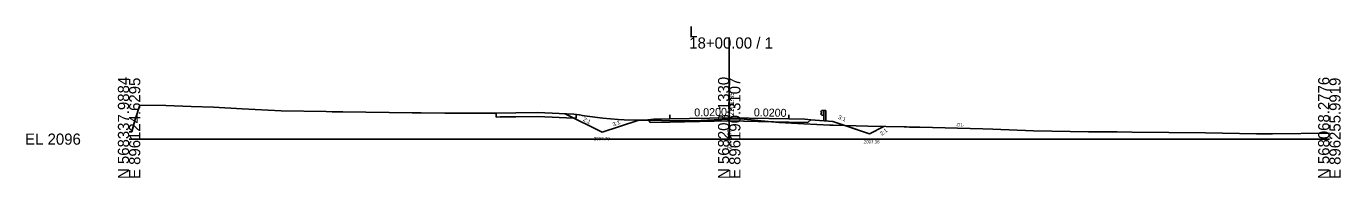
# Model space of a CAD drawing. Extents: x -26 to 1603, y -10 to 13527.
# Drawn here: x -25.7 to 302.8, y 5490.3 to 5528.3 of the extents above; entities that cross this region are included whole.
import ezdxf

# ---------------------------------------------------------------- set-up
doc = ezdxf.new("R2010")
doc.units = 0
for name, color, linetype in [('Default', 7, 'Continuous'), ('Exist XS Center Line Elevation Label', 7, 'Continuous'), ('Exist XS Ground Line', 7, 'Continuous'), ('Old_Level_61', 7, 'Continuous'), ('Old_Level_63', 7, 'Continuous'), ('Prop XS Ditch Slope Text', 7, 'Continuous'), ('Prop XS Ditch Standard Text', 7, 'Continuous'), ('Prop XS Earthwork Shape', 7, 'Continuous'), ('Prop XS EOT Tick Mark', 7, 'Continuous'), ('Prop XS Finish Grade', 7, 'Continuous'), ('Prop XS Finish Grade Earthwork', 7, 'Continuous'), ('Prop XS Finish Grade Paved Shoulder', 7, 'Continuous'), ('Prop XS Finish Grade Pavement', 7, 'Continuous'), ('Prop XS Guardrail', 7, 'Continuous'), ('Prop XS Side Slope Text', 7, 'Continuous'), ('Prop XS Subgrade Earthwork', 7, 'Continuous'), ('Prop XSC Text', 7, 'Continuous')]:
    doc.layers.add(name, color=color, linetype=linetype)

msp = doc.modelspace()

# ---------------------------------------------------------------- linework, layer by layer
at = {"layer": 'Exist XS Ground Line'}
for p, q in [((1.47, 5504.68), (2.66, 5508.5)), ((2.66, 5508.5), (9.21, 5508.43)), ((9.21, 5508.43), (15.51, 5508.21)), ((15.51, 5508.21), (21.06, 5507.97)), ((21.06, 5507.97), (28.3, 5507.58)), ((28.3, 5507.58), (38.03, 5507.12)), ((38.03, 5507.12), (49.22, 5506.88)), ((49.22, 5506.88), (50.76, 5506.85)), ((50.76, 5506.85), (53.46, 5506.83)), ((53.46, 5506.83), (70.76, 5506.62)), ((70.76, 5506.62), (73.04, 5506.59)), ((73.04, 5506.59), (78.93, 5506.49)), ((78.93, 5506.49), (90.15, 5506.53)), ((90.15, 5506.53), (91.73, 5506.53)), ((91.73, 5506.53), (96.69, 5506.61)), ((96.69, 5506.61), (102.07, 5506.7)), ((102.07, 5506.7), (111.16, 5506.24)), ((111.16, 5506.24), (111.77, 5506.21)), ((111.77, 5506.21), (112.54, 5506.05)), ((0.68, 5501.79), (1.47, 5504.68)), ((112.54, 5506.05), (113.29, 5505.9)), ((113.29, 5505.9), (113.8, 5505.8)), ((113.8, 5505.8), (118.37, 5505.29)), ((118.37, 5505.29), (122.24, 5504.89)), ((122.24, 5504.89), (123.74, 5504.83)), ((123.74, 5504.83), (133.06, 5504.65)), ((133.06, 5504.65), (137.76, 5504.56)), ((137.76, 5504.56), (141.34, 5504.61)), ((141.34, 5504.61), (146.25, 5504.86)), ((146.25, 5504.86), (150, 5504.98)), ((150, 5504.98), (152.88, 5505.07)), ((152.88, 5505.07), (160.6, 5504.36)), ((160.6, 5504.36), (162.47, 5504.19)), ((162.47, 5504.19), (168.69, 5503.86)), ((168.69, 5503.86), (175.19, 5503.5)), ((175.19, 5503.5), (175.99, 5503.48)), ((175.99, 5503.48), (184.67, 5503.23)), ((184.67, 5503.23), (193.7, 5503.07)), ((193.7, 5503.07), (194.29, 5503.06)), ((194.29, 5503.06), (195.07, 5503.02)), ((195.07, 5503.02), (197.68, 5502.99)), ((197.68, 5502.99), (213.4, 5502.6)), ((0, 5501.79), (0.68, 5501.79)), ((213.4, 5502.6), (215.93, 5502.52)), ((215.93, 5502.52), (226.05, 5502.05)), ((226.05, 5502.05), (239.84, 5501.83)), ((239.84, 5501.83), (246.96, 5501.8)), ((246.96, 5501.8), (250.7, 5501.74)), ((250.7, 5501.74), (269.05, 5501.57)), ((269.05, 5501.57), (281.78, 5501.33)), ((281.78, 5501.33), (283.05, 5501.31)), ((283.05, 5501.31), (285.82, 5501.34)), ((285.82, 5501.34), (300, 5501.53))]:
    msp.add_line(p, q, dxfattribs=at)
at = {"layer": 'Old_Level_61'}
for p, q in [((91.73, 5506.53), (91.73, 5505.53)), ((111.77, 5505.21), (111.77, 5506.21)), ((91.73, 5505.53), (92.73, 5505.55)), ((92.73, 5505.55), (96.69, 5505.61)), ((96.69, 5505.61), (102.07, 5505.7)), ((102.07, 5505.7), (111.16, 5505.24)), ((111.16, 5505.24), (111.77, 5505.21))]:
    msp.add_line(p, q, dxfattribs=at)
at = {"layer": 'Old_Level_63'}
for p, q in [((150, 5500), (150, 5525.5)), ((0, 5500), (150, 5500)), ((150, 5500), (300, 5500))]:
    msp.add_line(p, q, dxfattribs=at)
at = {"layer": 'Prop XS Earthwork Shape'}
for points in [[(111.16, 5506.24), (111.77, 5506.21), (112.54, 5506.05), (113.29, 5505.9), (113.8, 5505.8), (118.37, 5505.29), (122.24, 5504.89), (123.74, 5504.83), (128.22, 5504.74), (127.14, 5504.66), (118.27, 5501.7), (108.98, 5506.35)], [(129.65, 5504.86), (128.22, 5504.74), (129.79, 5504.71)], [(150, 5504.98), (152.88, 5505.07), (160.6, 5504.36), (160.79, 5504.35), (150, 5504.56), (135.14, 5504.26), (130.33, 5504.17), (129.79, 5504.71), (133.06, 5504.65), (137.76, 5504.56), (141.34, 5504.61), (146.25, 5504.86)], [(175.99, 5503.48), (178.92, 5503.4), (175.86, 5504.42), (170.36, 5504.86), (169.67, 5504.17), (164.86, 5504.26), (160.79, 5504.35), (162.47, 5504.19), (168.69, 5503.86), (175.19, 5503.5)], [(184.67, 5503.23), (188.63, 5503.16), (185.03, 5501.36), (178.92, 5503.4)]]:
    msp.add_lwpolyline(points, close=True, dxfattribs=at)
at = {"layer": 'Prop XS EOT Tick Mark'}
for p, q in [((135.14, 5505.06), (135.14, 5506.06)), ((164.86, 5505.06), (164.86, 5506.06))]:
    msp.add_line(p, q, dxfattribs=at)
at = {"layer": 'Prop XS Finish Grade'}
for p, q in [((131.14, 5504.98), (129.65, 5504.86)), ((168.86, 5504.98), (170.36, 5504.86))]:
    msp.add_line(p, q, dxfattribs=at)
at = {"layer": 'Prop XS Finish Grade Earthwork'}
for p, q in [((118.27, 5501.7), (108.98, 5506.35)), ((127.14, 5504.66), (118.27, 5501.7)), ((129.65, 5504.86), (127.14, 5504.66)), ((170.36, 5504.86), (175.86, 5504.42)), ((175.86, 5504.42), (185.03, 5501.36)), ((185.03, 5501.36), (188.63, 5503.16))]:
    msp.add_line(p, q, dxfattribs=at)
at = {"layer": 'Prop XS Finish Grade Paved Shoulder'}
for p, q in [((135.14, 5505.06), (131.14, 5504.98)), ((164.86, 5505.06), (168.86, 5504.98))]:
    msp.add_line(p, q, dxfattribs=at)
at = {"layer": 'Prop XS Finish Grade Pavement'}
for p, q in [((135.14, 5505.06), (150, 5505.35)), ((150, 5505.35), (164.86, 5505.06))]:
    msp.add_line(p, q, dxfattribs=at)
at = {"layer": 'Prop XS Guardrail'}
for p, q in [((172.86, 5506.96), (172.83, 5506.9)), ((172.83, 5506.9), (172.86, 5506.84)), ((172.86, 5506.34), (172.83, 5506.28)), ((172.83, 5506.28), (172.86, 5506.22)), ((173.15, 5507.16), (172.86, 5506.96)), ((172.86, 5506.84), (173.15, 5506.64)), ((173.15, 5506.54), (172.86, 5506.34)), ((172.86, 5506.22), (173.15, 5506.02)), ((173.65, 5507.16), (173.15, 5507.16)), ((173.15, 5506.64), (173.15, 5506.54)), ((173.65, 5507.16), (173.65, 5504.66)), ((174.15, 5507.16), (173.65, 5507.16)), ((174.15, 5504.66), (174.15, 5507.16)), ((173.15, 5506.02), (173.65, 5506.02))]:
    msp.add_line(p, q, dxfattribs=at)
at = {"layer": 'Prop XS Subgrade Earthwork'}
for p, q in [((130.33, 5504.17), (129.65, 5504.86)), ((135.14, 5504.26), (130.33, 5504.17)), ((150, 5504.56), (135.14, 5504.26)), ((164.86, 5504.26), (150, 5504.56)), ((164.86, 5504.26), (169.67, 5504.17)), ((169.67, 5504.17), (170.36, 5504.86))]:
    msp.add_line(p, q, dxfattribs=at)

# ---------------------------------------------------------------- texts
at = {"layer": 'Default'}
for rotation, p in [(1.1458, (141.28, 5505.68)), (358.8542, (156.14, 5505.73))]:
    msp.add_text('0.0200', height=2, rotation=rotation, dxfattribs=at).set_placement(p)
at = {"layer": 'Exist XS Center Line Elevation Label'}
msp.add_text('2100.98', height=1, rotation=90, dxfattribs=at).set_placement((150.5, 5497.41))
at = {"layer": 'Old_Level_63'}
for s, p in [('L', (140, 5525.5)), ('18+00.00 / 1', (140, 5522.7)), ('EL 2096', (-26, 5498.6))]:
    msp.add_text(s, height=2.8, dxfattribs=at).set_placement(p)
for s, p in [('N 568337.9884', (0, 5490)), ('E 896124.6295', (2.8, 5490)), ('N 568203.1330', (150, 5490)), ('E 896190.3107', (152.8, 5490)), ('N 568068.2776', (300, 5490)), ('E 896255.9919', (302.8, 5490))]:
    msp.add_text(s, height=2.8, rotation=90, dxfattribs=at).set_placement(p)
at = {"layer": 'Prop XS Ditch Slope Text'}
msp.add_text('3:1', height=1, rotation=21.7366, dxfattribs=at).set_placement((121.08, 5503.15))
at = {"layer": 'Prop XS Ditch Standard Text'}
for s, p in [('-D1-', (206.6, 5503.2)), ('2097.70', (116.14, 5499.72)), ('2097.36', (183.59, 5498.92))]:
    msp.add_text(s, height=0.8, dxfattribs=at).set_placement(p)
at = {"layer": 'Prop XS Side Slope Text'}
for s, rotation, p in [('2:1', 333.4382, (113.36, 5504.63)), ('3:1', 338.821, (177.15, 5505.1)), ('2:1', 37.5433, (188.13, 5500.82))]:
    msp.add_text(s, height=1, rotation=rotation, dxfattribs=at).set_placement(p)
at = {"layer": 'Prop XSC Text'}
msp.add_text(' 2101.35', height=1.2, rotation=90, dxfattribs=at).set_placement((151.2, 5505.35))

doc.saveas('drawing.dxf')
